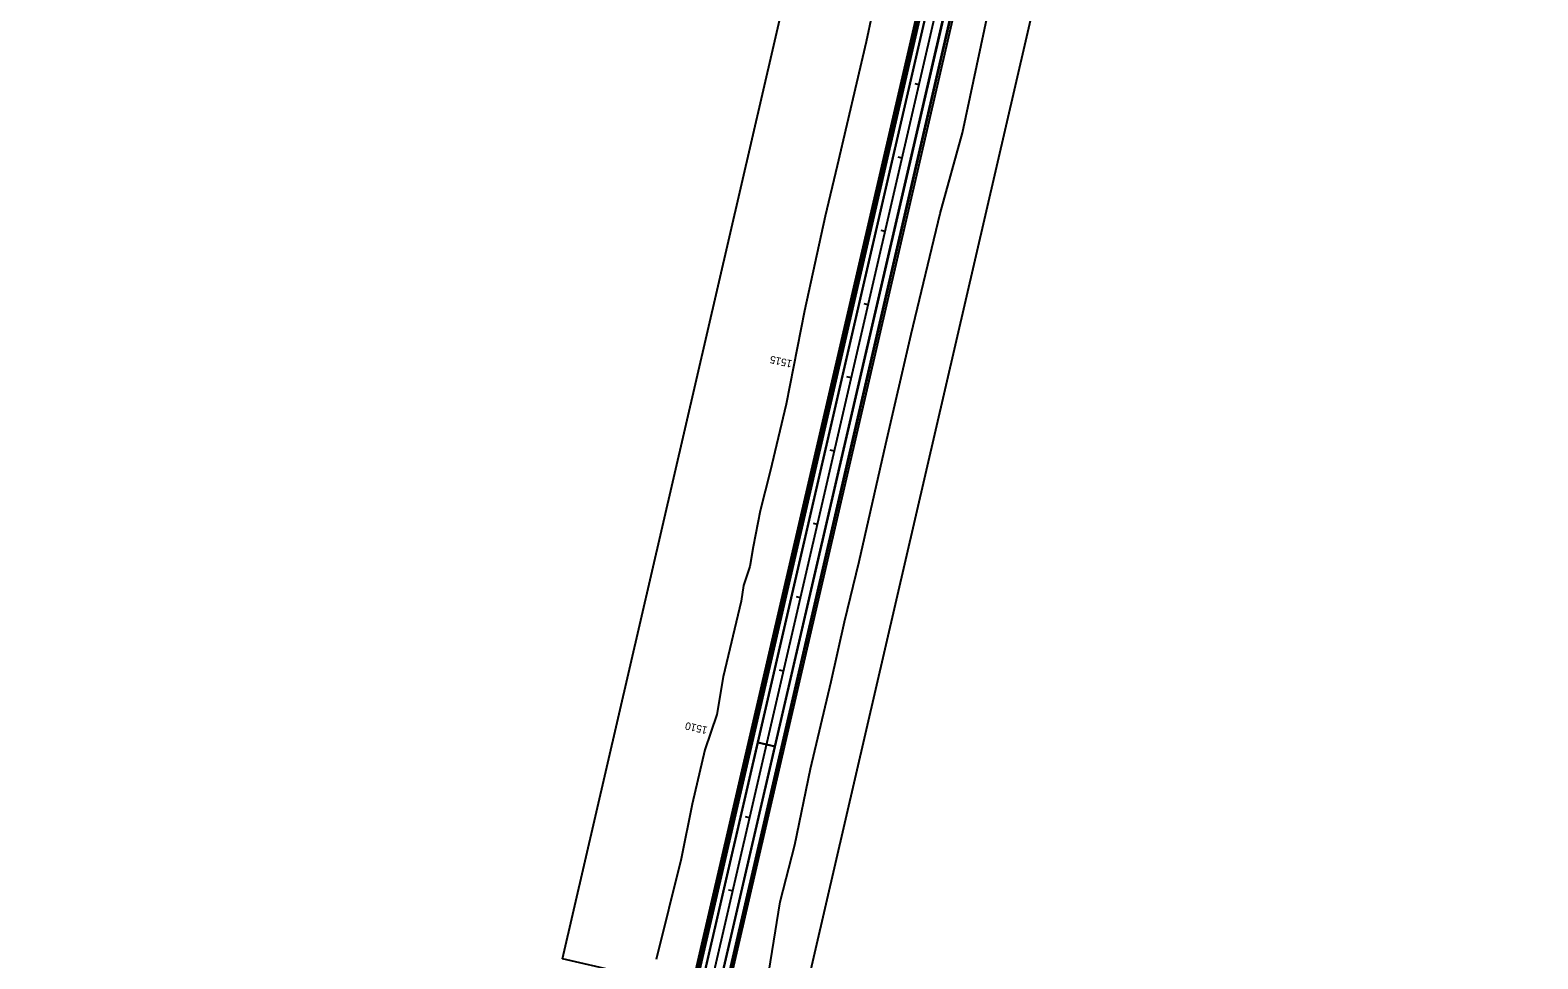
# Model space of a CAD drawing. Extents: x 21596487 to 21601936, y 8263704 to 8275922.
# Drawn here: x 21596705 to 21598711, y 8271050 to 8272284 of the extents above; entities that cross this region are included whole.
import ezdxf

# ---------------------------------------------------------------- set-up
doc = ezdxf.new("R2010")
doc.units = 0
for name, color, linetype in [('Default', 7, 'Continuous'), ('dsnGroundLineIntercept', 7, 'Continuous'), ('dsnPaintPlaceBrokenCenterLineYellow', 7, 'Continuous'), ('dsnPaintPlaceDottedLineYellow', 7, 'Continuous'), ('dsnXsROWLabelLineExist', 7, 'Continuous'), ('EdgeUnpaved', 7, 'Continuous'), ('ErosionControl', 7, 'Continuous'), ('Joints', 7, 'Continuous'), ('TC_DNC', 7, 'Continuous'), ('TC_GranularBackFill', 7, 'Continuous'), ('TC_MacadamStone', 7, 'Continuous'), ('TC_SpecialBackfill', 7, 'Continuous'), ('Wall', 7, 'Continuous')]:
    doc.layers.add(name, color=color, linetype=linetype)

msp = doc.modelspace()

# ---------------------------------------------------------------- linework, layer by layer
at = {"layer": 'Default'}
msp.add_line((21596728.7, 8267202.6), (21598588.8, 8275242.6), dxfattribs=at)
msp.add_line((21596728.7, 8267202.6), (21598588.8, 8275242.6), dxfattribs=at)
at = {"layer": 'dsnGroundLineIntercept'}
for points in [[(21597681.7, 8270993.6), (21597702.8, 8271125.4), (21597722.2, 8271201.3), (21597743.1, 8271302.5), (21597770.5, 8271418.5), (21597788.4, 8271497.6), (21597808, 8271578), (21597843.3, 8271734.3), (21597877.2, 8271880.3), (21597915.6, 8272040.5), (21597945.4, 8272147.9), (21597989.1, 8272354.3), (21598011.6, 8272452.4), (21598042.8, 8272590.9), (21598072.4, 8272707.8), (21598113.7, 8272875.1), (21598126.3, 8272921.7), (21598149.1, 8273013.3), (21598158.8, 8273052.7), (21598177.9, 8273134.5), (21598205.6, 8273266.1), (21598247.8, 8273437.8), (21598254.9, 8273463), (21598281, 8273577.1)], [(21597824.8, 8272304.1), (21597817.4, 8272268.9), (21597778.7, 8272104), (21597762.9, 8272036.9), (21597735.4, 8271911.2), (21597710.6, 8271787.3), (21597689.4, 8271697.5), (21597676.1, 8271645.4), (21597666.8, 8271597.7), (21597662.5, 8271571.2), (21597653.9, 8271546.1), (21597650.9, 8271525.1), (21597627, 8271424.7), (21597618.7, 8271374.6), (21597602.5, 8271327.5), (21597585.6, 8271255.4), (21597571.1, 8271182.5), (21597538, 8271048.7)]]:
    msp.add_lwpolyline(points, dxfattribs=at)
at = {"layer": 'dsnPaintPlaceBrokenCenterLineYellow'}
msp.add_line((21597006.2, 8268402), (21598343, 8274180.5), dxfattribs=at)
at = {"layer": 'dsnPaintPlaceDottedLineYellow'}
for p, q in [((21596717, 8267205.3), (21598523, 8275011.8)), ((21596739.7, 8267200), (21598545.7, 8275006.6))]:
    msp.add_line(p, q, dxfattribs=at)
at = {"layer": 'dsnXsROWLabelLineExist'}
for p, q in [((21596850.5, 8267174.4), (21598710.5, 8275214.5)), ((21597413.5, 8271049.8), (21597926.3, 8273266.6)), ((21597486.5, 8271032.9), (21597413.5, 8271049.8))]:
    msp.add_line(p, q, dxfattribs=at)
at = {"layer": 'EdgeUnpaved'}
for p, q in [((21596709.9, 8267206.9), (21598472.3, 8274824.9)), ((21596710.4, 8267206.8), (21598472.9, 8274825.4))]:
    msp.add_line(p, q, dxfattribs=at)
at = {"layer": 'ErosionControl'}
for p, q in [((21597887.6, 8272211.7), (21597882.2, 8272212.9)), ((21597865, 8272114.3), (21597859.7, 8272115.5)), ((21597842.5, 8272016.8), (21597837.1, 8272018.1)), ((21597819.9, 8271919.4), (21597814.6, 8271920.6)), ((21597797.4, 8271822), (21597791.4, 8271823.4)), ((21597774.9, 8271724.6), (21597769.5, 8271725.8)), ((21597752.3, 8271627.1), (21597747, 8271628.4)), ((21597729.8, 8271529.7), (21597724.4, 8271530.9)), ((21597707.2, 8271432.3), (21597701.9, 8271433.5)), ((21597684.7, 8271334.8), (21597678.7, 8271336.2)), ((21597662.2, 8271237.4), (21597656.8, 8271238.7)), ((21597639.6, 8271140), (21597634.3, 8271141.2))]:
    msp.add_line(p, q, dxfattribs=at)
at = {"layer": 'TC_DNC'}
for p, q in [((21596708, 8267207.3), (21598514, 8275013.9)), ((21596749.4, 8267197.8), (21598555.4, 8275004.4))]:
    msp.add_line(p, q, dxfattribs=at)
at = {"layer": 'TC_GranularBackFill'}
msp.add_line((21596728.7, 8267202.6), (21598588.8, 8275242.6), dxfattribs=at)
at = {"layer": 'TC_MacadamStone'}
for p, q in [((21596709.2, 8267207.1), (21598515.3, 8275013.6)), ((21596748.2, 8267198.1), (21598554.2, 8275004.6))]:
    msp.add_line(p, q, dxfattribs=at)
at = {"layer": 'TC_SpecialBackfill'}
for p, q in [((21598011.1, 8272799), (21597673, 8271337.5)), ((21597696.4, 8271332.1), (21598034.5, 8272793.5)), ((21597673, 8271337.5), (21597334.9, 8269876.1)), ((21597358.3, 8269870.7), (21597696.4, 8271332.1)), ((21597673, 8271337.5), (21597696.4, 8271332.1)), ((21597696.4, 8271332.1), (21597673, 8271337.5))]:
    msp.add_line(p, q, dxfattribs=at)
at = {"layer": 'Wall'}
for p, q in [((21596705.3, 8267208), (21598511.4, 8275014.5)), ((21596752.1, 8267197.2), (21598558.1, 8275003.7))]:
    msp.add_line(p, q, dxfattribs=at)

# ---------------------------------------------------------------- texts
at = {"layer": 'Joints'}
for s, p in [('1515', (21597719.5, 8271845.1)), ('1510', (21597606.8, 8271358))]:
    msp.add_text(s, height=10, rotation=166.974, dxfattribs=at).set_placement(p)

doc.saveas('drawing.dxf')
